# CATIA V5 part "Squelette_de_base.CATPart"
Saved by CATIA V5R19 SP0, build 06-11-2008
Part number: Squelette de base
Publications: "E", "Fig.3", "Fig.2", "C", "D", "as (BF)", "ap", "ab", "ar", "Droite.21", "Droite.18", "F"
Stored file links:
  J:\CFAO_IFMA\Squelette_de_base.CATPart
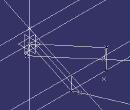
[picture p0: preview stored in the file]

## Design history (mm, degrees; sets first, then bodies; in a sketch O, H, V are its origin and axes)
Set1
  Point1 "E": (0, 0, 0)
  Plane1 "Fig.3": type Offset, RefPlane xy-plane, Offset 0
  Plane2 "Fig.2": type Offset, RefPlane yz-plane, Offset 0
  Set2 "Fig.3"
    Point2 "C''": type OnPlane, Support Plane1, RefPoint Point7, H 130, V 0, Direction (1, 0, 0)
    Point3 "F": type OnPlane, Support Plane1, RefPoint Point5, H -400, V 0, Direction (1, 0, 0)
    Line1 "EC''": type PtPt, FirstPoint Point1, SecondPoint Point2
    Line2 "EF": type PtPt, FirstPoint Point1, SecondPoint Point3
    Line3 "D\"C\"": type PtDir, RefPoint Point2, Direction Line2, Support Plane1, Start 0, End 0
    Line4 "D\"F\"": type PtDir, LineFirstUpto Line3, RefPoint Point3, Direction Line1, Start 0, End 0
    Point4 "D\"": (0, 0, 0), relative to vertex of Line4
  Set3 "Fig.2"
    Line5 "EC'": type PtPt, FirstPoint Point1, SecondPoint Point7
    Point5 "B": type OnPlane, Support Plane2, RefPoint Point1, H 470, V -220, Direction (0, 1, 0)
    Line6 "BE": type PtPt, FirstPoint Point5, SecondPoint Point1
    Line7 "BD'": type PtDir, RefPoint Point5, Direction Line5, Start 0, End 20
    Line8 "C'D'": type PtDir, LineFirstUpto Line7, RefPoint Point7, Direction Line6, Support Plane2, Start 0, End 0
    Point6 "D'": (0, 0, 0), relative to vertex of Line8
    Point7 "C'": type OnPlane, Support Plane2, RefPoint Point1, H 100, V 30, Direction (0, 1, 0)
  Set4 "Pour construction des points"
    Line9: type Normal, LineSecondUpto Point7, RefPoint Point2, RefSkin Plane1, Start 0, End 0
    Line10: type Normal, LineSecondUpto Line9, RefPoint Point7, RefSkin Plane2, Start 0, End 0
    Point8 "C": (0, 0, 0), relative to vertex of Line10
    Line11 "as (BF)": type Normal, RefPoint Point5, RefSkin Plane2, Start 0, End 0
    Line12 "ap": type Normal, LineSecondUpto Line11, RefPoint Point3, RefSkin Plane1, Start 0, End 0
    Point9: (0, 0, 0), relative to vertex of Line12
    Line13: type Normal, RefPoint Point4, RefSkin Plane1, Start 0, End 0
    Line14: type Normal, LineSecondUpto Line13, RefPoint Point6, RefSkin Plane2, Start 0, End 0
    Point10 "D": (0, 0, 0), relative to vertex of Line14
    Line15 "ab": type Normal, RefPoint Point1, RefSkin Plane2, Start 0, End 0
    Line16 "ar": type Normal, RefPoint Point1, RefSkin Plane1, Start 0, End 0
    Point11: type OnPlane, Support Plane2, H 0, V 150, Direction (0, 1, 0)
    Line17: type Angle, RefPoint Point11, Curve Line15, Start 0, End 0, Angle 0
    Line18: type PtDir, LineFirstUpto Line11, LineSecondUpto Line16, RefPoint Point11, Direction Line6, Start 0, End 0
    Line19: type PtDir, LineFirstUpto Line18, RefPoint Point5, Direction Line16, Start 0, End 0
    Line20: type PtDir, RefPoint vertex of Line19, Direction Line11, Start 0, End 0
Body1 (main body)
